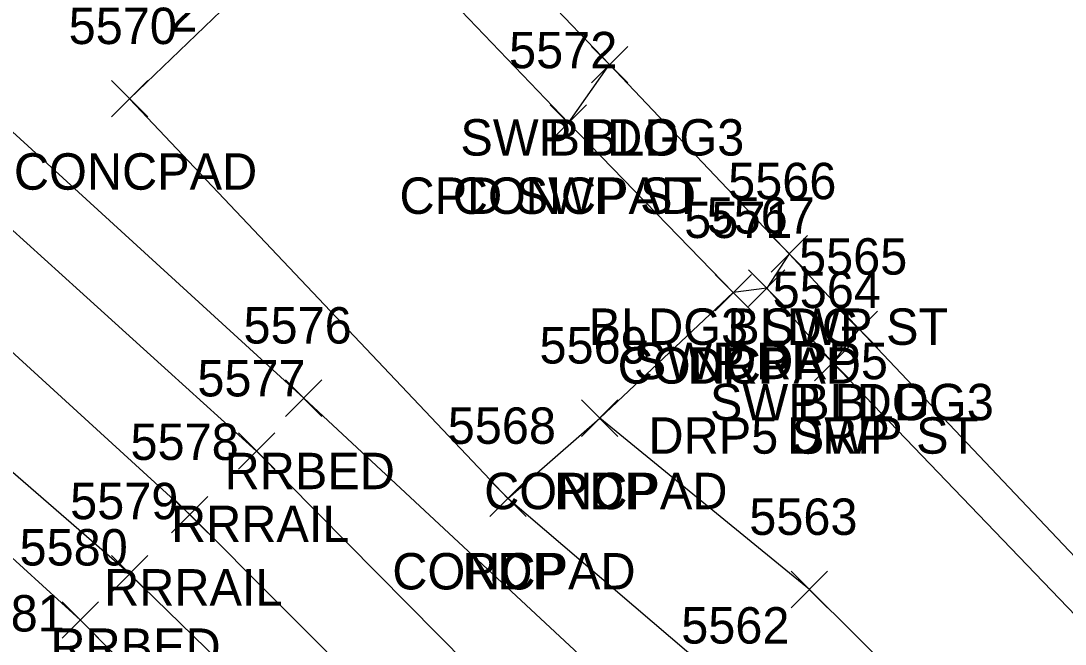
# Model space of a CAD drawing. Extents: x 1618146 to 1620418, y 640749 to 641927.
# Drawn here: x 1620120.5 to 1620177.9, y 641181.4 to 641215.6 of the extents above; entities that cross this region are included whole.
import ezdxf

# ---------------------------------------------------------------- set-up
doc = ezdxf.new("R2010")
doc.units = 0
for name, color, linetype in [('L_A', 7, 'Continuous'), ('L_I', 7, 'Continuous'), ('L_TIC', 7, 'Continuous'), ('LBC', 7, 'Continuous'), ('LELB', 7, 'Continuous'), ('LS', 7, 'Continuous'), ('P_A', 7, 'Continuous'), ('P_I', 7, 'Continuous'), ('P_TIC', 7, 'Continuous'), ('PET', 7, 'Continuous'), ('R_A', 7, 'Continuous'), ('R_I', 7, 'Continuous'), ('R_TIC', 7, 'Continuous'), ('RDP', 7, 'Continuous'), ('RR', 7, 'Continuous'), ('RRB', 7, 'Continuous'), ('RSW', 7, 'Continuous'), ('U_C', 7, 'Continuous')]:
    doc.layers.add(name, color=color, linetype=linetype)

msp = doc.modelspace()

# ---------------------------------------------------------------- linework, layer by layer
at = {"layer": 'L_TIC'}
for points in [[(1620151.839, 641212.225), (1620153.839, 641214.225)], [(1620153.839, 641212.225), (1620151.839, 641214.225)], [(1620125.449, 641210.351), (1620127.449, 641212.351)], [(1620127.449, 641210.351), (1620125.449, 641212.351)], [(1620149.572, 641209.022), (1620151.572, 641211.022)], [(1620151.572, 641209.022), (1620149.572, 641211.022)], [(1620161.715, 641201.828), (1620163.715, 641203.828)], [(1620163.715, 641201.828), (1620161.715, 641203.828)], [(1620158.631, 641199.696), (1620160.631, 641201.696)], [(1620160.631, 641199.696), (1620158.631, 641201.696)], [(1620165.556, 641197.685), (1620167.556, 641199.685)], [(1620167.556, 641197.685), (1620165.556, 641199.685)], [(1620151.297, 641192.8), (1620153.297, 641194.8)], [(1620153.297, 641192.8), (1620151.297, 641194.8)], [(1620146.247, 641188.39), (1620148.247, 641190.39)], [(1620148.247, 641188.39), (1620146.247, 641190.39)], [(1620146.247, 641188.39), (1620148.247, 641190.39)], [(1620148.247, 641188.39), (1620146.247, 641190.39)], [(1620122.748, 641181.705), (1620124.748, 641183.705)], [(1620124.748, 641181.705), (1620122.748, 641183.705)]]:
    msp.add_lwpolyline(points, dxfattribs=at)
at = {"layer": 'LBC'}
msp.add_lwpolyline([(1620215.058, 641244.302), (1620205.976, 641235.712), (1620202.677, 641232.585), (1620189.499, 641220.107), (1620199.083, 641211.828), (1620201.415, 641213.808), (1620202.472, 641212.521), (1620205.827, 641209.331), (1620206.941, 641208.229), (1620204.756, 641205.896), (1620213.685, 641196.392), (1620197.139, 641180.509), (1620189.981, 641173.967), (1620166.556, 641198.685), (1620162.715, 641202.828), (1620152.839, 641213.225), (1620141.669, 641224.901), (1620165.022, 641247.378), (1620169.209, 641243.063), (1620193.587, 641266.433)], dxfattribs=at)
at = {"layer": 'LELB'}
msp.add_lwpolyline([(1620198.161, 641096.651), (1620186.457, 641115.205), (1620172.223, 641131.175), (1620143.867, 641162.38), (1620123.748, 641182.705), (1620104.934, 641199.85), (1620097.932, 641205.844), (1620094.188, 641209.351)], dxfattribs=at)
at = {"layer": 'LS'}
for points in [[(1620147.247, 641189.39), (1620126.449, 641211.351), (1620138.364, 641222.789)], [(1620147.247, 641189.39), (1620152.297, 641193.8), (1620159.631, 641200.696), (1620150.572, 641210.022), (1620138.364, 641222.789)]]:
    msp.add_lwpolyline(points, dxfattribs=at)
at = {"layer": 'P_TIC'}
for points in [[(1620151.297, 641192.8), (1620153.297, 641194.8)], [(1620153.297, 641192.8), (1620151.297, 641194.8)], [(1620146.247, 641188.39), (1620148.247, 641190.39)], [(1620148.247, 641188.39), (1620146.247, 641190.39)], [(1620162.819, 641183.387), (1620164.819, 641185.387)], [(1620164.819, 641183.387), (1620162.819, 641185.387)]]:
    msp.add_lwpolyline(points, dxfattribs=at)
at = {"layer": 'PET'}
for points in [[(1620248.37, 641210.419), (1620247.05, 641196.867), (1620244.221, 641193.357), (1620231.184, 641173.763), (1620213.381, 641155.488), (1620202.395, 641145.525), (1620184.689, 641164.4), (1620181.462, 641166.888), (1620163.819, 641184.387), (1620152.297, 641193.8)], [(1620199.84, 641100.892), (1620190.476, 641119.747), (1620190.752, 641121.585), (1620192.149, 641127.788), (1620193.459, 641134.423), (1620190.666, 641144.593), (1620174.447, 641161.945), (1620160.08, 641178.417), (1620147.247, 641189.39)]]:
    msp.add_lwpolyline(points, dxfattribs=at)
at = {"layer": 'R_TIC'}
for points in [[(1620151.839, 641212.225), (1620153.839, 641214.225)], [(1620153.839, 641212.225), (1620151.839, 641214.225)], [(1620149.572, 641209.022), (1620151.572, 641211.022)], [(1620151.572, 641209.022), (1620149.572, 641211.022)], [(1620161.715, 641201.828), (1620163.715, 641203.828)], [(1620163.715, 641201.828), (1620161.715, 641203.828)], [(1620160.474, 641199.94), (1620162.474, 641201.94)], [(1620162.474, 641199.94), (1620160.474, 641201.94)], [(1620160.474, 641199.94), (1620162.474, 641201.94)], [(1620162.474, 641199.94), (1620160.474, 641201.94)], [(1620158.631, 641199.696), (1620160.631, 641201.696)], [(1620160.631, 641199.696), (1620158.631, 641201.696)], [(1620165.556, 641197.685), (1620167.556, 641199.685)], [(1620167.556, 641197.685), (1620165.556, 641199.685)], [(1620164.106, 641195.848), (1620166.106, 641197.848)], [(1620166.106, 641195.848), (1620164.106, 641197.848)], [(1620164.106, 641195.848), (1620166.106, 641197.848)], [(1620166.106, 641195.848), (1620164.106, 641197.848)], [(1620135.028, 641193.899), (1620137.028, 641195.899)], [(1620137.028, 641193.899), (1620135.028, 641195.899)], [(1620132.437, 641190.994), (1620134.437, 641192.994)], [(1620134.437, 641190.994), (1620132.437, 641192.994)], [(1620128.761, 641187.505), (1620130.761, 641189.505)], [(1620130.761, 641187.505), (1620128.761, 641189.505)], [(1620125.451, 641184.248), (1620127.451, 641186.248)], [(1620127.451, 641184.248), (1620125.451, 641186.248)]]:
    msp.add_lwpolyline(points, dxfattribs=at)
at = {"layer": 'RDP'}
msp.add_lwpolyline([(1620181.462, 641166.888), (1620188.251, 641172.756), (1620165.106, 641196.848), (1620161.474, 641200.94), (1620159.631, 641200.696)], dxfattribs=at)
at = {"layer": 'RR'}
for points in [[(1620192.149, 641127.788), (1620168.312, 641155.994), (1620153.359, 641171.838), (1620133.437, 641191.994), (1620110.111, 641213.081), (1620101.472, 641220.641), (1620055.356, 641258.678), (1620021.942, 641286.099), (1619984.199, 641317.184), (1619946.809, 641347.804), (1619927.299, 641363.881), (1619890.892, 641393.618), (1619862.546, 641416.891)], [(1620190.752, 641121.585), (1620164.758, 641152.663), (1620149.827, 641168.387), (1620129.761, 641188.505), (1620106.878, 641209.401), (1620098.404, 641216.876), (1620053.4, 641253.963), (1620018.83, 641282.236), (1619980.557, 641313.635), (1619944.224, 641343.671), (1619924.209, 641360.052), (1619888.22, 641389.605), (1619859.159, 641413.425)]]:
    msp.add_lwpolyline(points, dxfattribs=at)
at = {"layer": 'RRB'}
for points in [[(1620282.833, 641005.905), (1620262.956, 641036.105), (1620245.554, 641062.879), (1620222.8, 641095.958), (1620205.802, 641118.707), (1620193.459, 641134.423), (1620171.398, 641158.878), (1620156.473, 641175.88), (1620136.028, 641194.899), (1620112.946, 641215.974), (1620104.578, 641223.126), (1620095.968, 641212.166)], [(1620271.861, 640991.557), (1620248.91, 641026.87), (1620231.317, 641051.296), (1620208.546, 641087.677), (1620199.84, 641100.892), (1620189.043, 641115.525), (1620174.379, 641133.159), (1620146.778, 641165.447), (1620126.451, 641185.248), (1620103.318, 641205.304), (1620095.968, 641212.166)]]:
    msp.add_lwpolyline(points, dxfattribs=at)
at = {"layer": 'RSW'}
for points in [[(1620150.572, 641210.022), (1620152.839, 641213.225)], [(1620162.715, 641202.828), (1620161.474, 641200.94)], [(1620165.106, 641196.848), (1620166.556, 641198.685)]]:
    msp.add_lwpolyline(points, dxfattribs=at)

# ---------------------------------------------------------------- texts
at = {"layer": 'L_A'}
for s, p in [('BLDG', (1620149.43, 641208.225)), ('CONCPAD', (1620120.094, 641206.351)), ('CONCPAD', (1620144.218, 641205.022)), ('BLDG', (1620159.306, 641197.828)), ('CONCPAD', (1620153.277, 641195.696)), ('BLDG', (1620163.146, 641193.685)), ('CONCPAD', (1620145.942, 641188.8)), ('CONCPAD', (1620140.893, 641184.39)), ('CONCPAD', (1620140.893, 641184.39))]:
    msp.add_text(s, height=2, dxfattribs=at).set_placement(p)
at = {"layer": 'L_I'}
for s, p in [('5570', (1620123.102, 641214.351)), ('5572', (1620147.312, 641213.022)), ('5566', (1620159.353, 641205.828)), ('5571', (1620156.939, 641203.696)), ('5565', (1620163.249, 641201.685)), ('5569', (1620148.982, 641196.8)), ('5568', (1620143.94, 641192.39)), ('5568', (1620143.94, 641192.39)), ('5580', (1620120.402, 641185.705)), ('5581', (1620116.941, 641182.081))]:
    msp.add_text(s, height=2, dxfattribs=at).set_placement(p)
at = {"layer": 'P_A'}
for p in [(1620149.785, 641188.8), (1620144.736, 641184.39)]:
    msp.add_text('RDP', height=2, dxfattribs=at).set_placement(p)
at = {"layer": 'P_I'}
for s, p in [('5569', (1620148.982, 641196.8)), ('5568', (1620143.94, 641192.39)), ('5563', (1620160.512, 641187.387)), ('5562', (1620156.773, 641181.417))]:
    msp.add_text(s, height=2, dxfattribs=at).set_placement(p)
at = {"layer": 'R_A'}
for s, p in [('SWP BLDG3', (1620144.634, 641208.225)), ('CPD SWP ST', (1620141.288, 641205.022)), ('BLDG3 SWP ST', (1620151.684, 641197.828)), ('SWP DRP5', (1620154.167, 641195.94)), ('DRP', (1620158.962, 641195.94)), ('DRP', (1620157.119, 641195.696)), ('SWP BLDG3', (1620158.351, 641193.685)), ('DRP5 SWP ST', (1620154.973, 641191.848)), ('DRP', (1620162.594, 641191.848)), ('RRBED', (1620131.674, 641189.899)), ('RRRAIL', (1620128.728, 641186.994)), ('RRRAIL', (1620125.052, 641183.505)), ('RRBED', (1620122.097, 641180.248))]:
    msp.add_text(s, height=2, dxfattribs=at).set_placement(p)
at = {"layer": 'R_I'}
for s, p in [('5572', (1620147.312, 641213.022)), ('5566', (1620159.353, 641205.828)), ('5567', (1620158.167, 641203.94)), ('5567', (1620158.167, 641203.94)), ('5571', (1620156.939, 641203.696)), ('5565', (1620163.249, 641201.685)), ('5564', (1620161.799, 641199.848)), ('5564', (1620161.799, 641199.848)), ('5576', (1620132.713, 641197.899)), ('5577', (1620130.177, 641194.994)), ('5578', (1620126.501, 641191.505)), ('5579', (1620123.184, 641188.248))]:
    msp.add_text(s, height=2, dxfattribs=at).set_placement(p)
at = {"layer": 'U_C'}
msp.add_text('2', height=2, dxfattribs=at).set_placement((1620128.687, 641215.041))

doc.saveas('drawing.dxf')
